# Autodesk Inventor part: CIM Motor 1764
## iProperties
Created: 2008-01
Part Number: CIM Motor 1764
Document SubType Name: Modeling
Designer: gstuder
Density: 1 g/cm^3
Mass: 1474.17 g
Surface Area: 428.563 cm^2
Volume: 334.464 cm^3
Catalog Web Link: ifirobotics.
Description: 2.5" CIM Motor
Author: gstuder
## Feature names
1. Extrusion1
2. Fillet1
3. Extrusion3
4. Mirror1
5. Chamfer1
6. Extrusion4
7. Extrusion5
8. Extrusion6
9. Chamfer2
10. Extrusion7
11. Extrusion8
12. Fillet2
13. Chamfer3
14. Hole1
15. Extrusion9
16. Extrusion10
17. Extrusion11
18. Extrusion12
19. Extrusion13
20. Extrusion14
21. Extrusion15
22. Chamfer4
23. Revolution1
24. Extrusion16
25. Circular Pattern1
